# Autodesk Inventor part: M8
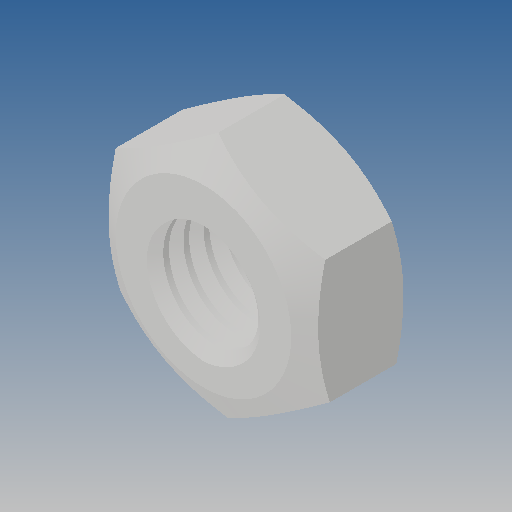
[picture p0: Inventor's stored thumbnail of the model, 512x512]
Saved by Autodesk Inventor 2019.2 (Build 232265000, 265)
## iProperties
Created: 2012-09
Part Number: M8
Material: Ogólny
Document SubType Name: Modeling
Designer: CADENGINEERING4
Density: 1 g/cm^3
Appearance: Domyślna
Author: CADENGINEERING4
Revision Number: ÈÎºÎ
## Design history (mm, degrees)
feature "ÇÐ³ý-É¨Ãè1"
node "Bryła1"
